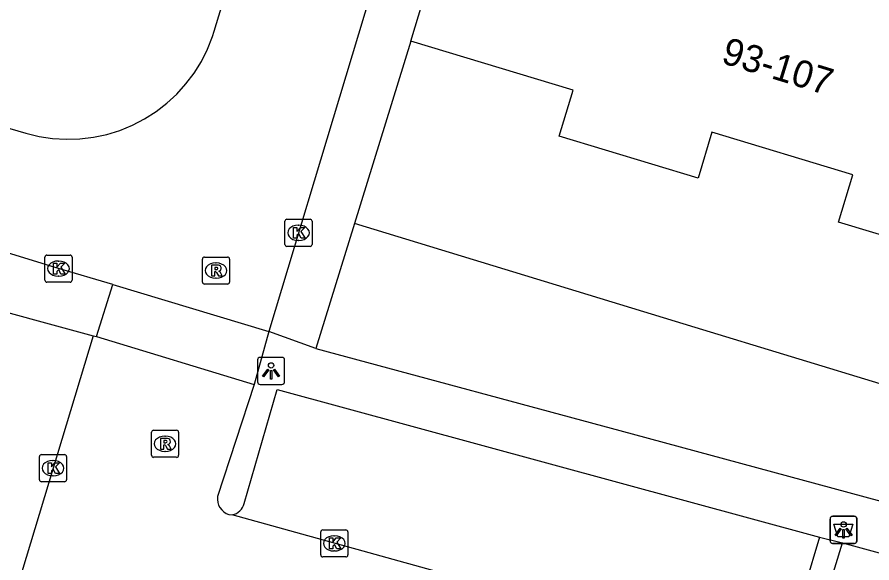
# Model space of a CAD drawing. Extents: x 160304 to 160954, y 383686 to 384161.
# Drawn here: x 160759.25 to 160790.81, y 383754.16 to 383774.29 of the extents above; entities that cross this region are included whole.
import ezdxf

# ---------------------------------------------------------------- set-up
doc = ezdxf.new("R2010")
doc.units = 0
for name, color, linetype in [('IMGEO_Afvalbak', 7, 'Continuous'), ('IMGEO_Groenvoorziening', 7, 'Continuous'), ('IMGEO_Kolk', 7, 'Continuous'), ('IMGEO_Lichtpunt', 7, 'Continuous'), ('IMGEO_Pand', 7, 'Continuous'), ('IMGEO_Pand_nummerreeks', 7, 'Continuous'), ('IMGEO_Rijbaan_lokaal_open', 7, 'Continuous'), ('IMGEO_Rioolput', 7, 'Continuous'), ('IMGEO_Voetpad_open', 7, 'Continuous')]:
    doc.layers.add(name, color=color, linetype=linetype)

msp = doc.modelspace()

# ---------------------------------------------------------------- linework, layer by layer
at = {"layer": 'IMGEO_Afvalbak'}
for p, q in [((160789.267, 383754.975), (160789.267, 383755.775)), ((160789.267, 383755.775), (160789.267, 383754.975)), ((160789.367, 383755.875), (160790.157, 383755.875)), ((160790.157, 383755.875), (160789.367, 383755.875)), ((160790.257, 383755.775), (160790.257, 383754.975)), ((160790.257, 383754.975), (160790.257, 383755.775)), ((160790.157, 383754.875), (160789.367, 383754.875)), ((160789.367, 383754.875), (160790.157, 383754.875))]:
    msp.add_line(p, q, dxfattribs=at)
msp.add_lwpolyline([(160789.41, 383755.589), (160790.114, 383755.589), (160789.965, 383755.119), (160789.559, 383755.119), (160789.41, 383755.589)], dxfattribs=at)
for centre, start, end in [((160789.367, 383755.775), 90, 180), ((160789.367, 383755.775), 90, 180), ((160790.157, 383755.775), 0, 90), ((160790.157, 383755.775), 360, 90), ((160789.367, 383754.975), 180, 270), ((160789.367, 383754.975), 180, 270), ((160790.157, 383754.975), 270, 0), ((160790.157, 383754.975), 270, 0)]:
    msp.add_arc(centre, 0.1, start, end, dxfattribs=at)
at = {"layer": 'IMGEO_Groenvoorziening'}
msp.add_lwpolyline([(160798.517, 383758.511), (160784.286, 383762.843), (160783.114, 383763.2), (160771.703, 383766.673)], dxfattribs=at)
at = {"layer": 'IMGEO_Kolk'}
for p, q in [((160769.214, 383766.835), (160770.066, 383766.835)), ((160769.139, 383765.909), (160769.139, 383766.761)), ((160769.627, 383766.615), (160769.652, 383766.615)), ((160770.14, 383766.761), (160770.14, 383765.909)), ((160769.65, 383766.055), (160769.625, 383766.055)), ((160770.066, 383765.835), (160769.214, 383765.835)), ((160760.275, 383764.587), (160760.275, 383765.439)), ((160760.35, 383765.513), (160761.202, 383765.513)), ((160760.763, 383765.293), (160760.788, 383765.293)), ((160761.276, 383765.439), (160761.276, 383764.587)), ((160760.786, 383764.733), (160760.761, 383764.733)), ((160761.202, 383764.513), (160760.35, 383764.513)), ((160760.072, 383757.226), (160760.072, 383758.078)), ((160760.147, 383758.152), (160760.999, 383758.152)), ((160761.073, 383758.078), (160761.073, 383757.226)), ((160760.56, 383757.932), (160760.585, 383757.932)), ((160760.583, 383757.372), (160760.558, 383757.372)), ((160760.999, 383757.152), (160760.147, 383757.152)), ((160770.46, 383754.45), (160770.46, 383755.302)), ((160770.535, 383755.376), (160771.387, 383755.376)), ((160770.948, 383755.156), (160770.973, 383755.156)), ((160771.461, 383755.302), (160771.461, 383754.45)), ((160770.971, 383754.596), (160770.946, 383754.596)), ((160771.387, 383754.376), (160770.535, 383754.376))]:
    msp.add_line(p, q, dxfattribs=at)
for points in [[(160769.214, 383766.835), (160770.066, 383766.835)], [(160769.139, 383765.909), (160769.139, 383766.761)], [(160769.46, 383766.535), (160769.583, 383766.535), (160769.583, 383766.384), (160769.713, 383766.535), (160769.877, 383766.535), (160769.731, 383766.384), (160769.884, 383766.135), (160769.732, 383766.135), (160769.647, 383766.299), (160769.583, 383766.232), (160769.583, 383766.135), (160769.46, 383766.135), (160769.46, 383766.535)], [(160770.14, 383766.761), (160770.14, 383765.909)], [(160770.066, 383765.835), (160769.214, 383765.835)], [(160760.275, 383764.587), (160760.275, 383765.439)], [(160760.35, 383765.513), (160761.202, 383765.513)], [(160761.276, 383765.439), (160761.276, 383764.587)], [(160760.596, 383765.213), (160760.719, 383765.213), (160760.719, 383765.062), (160760.849, 383765.213), (160761.013, 383765.213), (160760.867, 383765.062), (160761.02, 383764.813), (160760.868, 383764.813), (160760.783, 383764.977), (160760.719, 383764.91), (160760.719, 383764.813), (160760.596, 383764.813), (160760.596, 383765.213)], [(160761.202, 383764.513), (160760.35, 383764.513)], [(160760.072, 383757.226), (160760.072, 383758.078)], [(160760.147, 383758.152), (160760.999, 383758.152)], [(160761.073, 383758.078), (160761.073, 383757.226)], [(160760.393, 383757.852), (160760.516, 383757.852), (160760.516, 383757.701), (160760.646, 383757.852), (160760.81, 383757.852), (160760.664, 383757.701), (160760.817, 383757.452), (160760.665, 383757.452), (160760.58, 383757.616), (160760.516, 383757.549), (160760.516, 383757.452), (160760.393, 383757.452), (160760.393, 383757.852)], [(160760.999, 383757.152), (160760.147, 383757.152)], [(160770.46, 383754.45), (160770.46, 383755.302)], [(160770.535, 383755.376), (160771.387, 383755.376)], [(160771.461, 383755.302), (160771.461, 383754.45)], [(160770.781, 383755.076), (160770.904, 383755.076), (160770.904, 383754.925), (160771.034, 383755.076), (160771.198, 383755.076), (160771.052, 383754.925), (160771.205, 383754.676), (160771.053, 383754.676), (160770.968, 383754.84), (160770.904, 383754.773), (160770.904, 383754.676), (160770.781, 383754.676), (160770.781, 383755.076)], [(160771.387, 383754.376), (160770.535, 383754.376)]]:
    msp.add_lwpolyline(points, dxfattribs=at)
for centre, start, end in [((160769.216, 383766.759), 91.552, 178.448), ((160769.216, 383766.759), 91.552, 178.448), ((160770.064, 383766.759), 1.552, 88.448), ((160770.064, 383766.759), 1.552, 88.448), ((160769.216, 383765.911), 181.552, 268.448), ((160769.216, 383765.911), 181.552, 268.448), ((160770.064, 383765.911), 271.552, 358.448), ((160770.064, 383765.911), 271.552, 358.448), ((160760.352, 383765.437), 91.552, 178.448), ((160760.352, 383765.437), 91.552, 178.448), ((160761.2, 383765.437), 1.552, 88.448), ((160761.2, 383765.437), 1.552, 88.448), ((160760.352, 383764.589), 181.552, 268.448), ((160760.352, 383764.589), 181.552, 268.448), ((160761.2, 383764.589), 271.552, 358.448), ((160761.2, 383764.589), 271.552, 358.448), ((160760.149, 383758.076), 91.552, 178.448), ((160760.149, 383758.076), 91.552, 178.448), ((160760.997, 383758.076), 1.552, 88.448), ((160760.997, 383758.076), 1.552, 88.448), ((160760.149, 383757.228), 181.552, 268.448), ((160760.149, 383757.228), 181.552, 268.448), ((160760.997, 383757.228), 271.552, 358.448), ((160760.997, 383757.228), 271.552, 358.448), ((160770.537, 383755.3), 91.552, 178.448), ((160770.537, 383755.3), 91.552, 178.448), ((160771.385, 383755.3), 1.552, 88.448), ((160771.385, 383755.3), 1.552, 88.448), ((160770.537, 383754.452), 181.552, 268.448), ((160770.537, 383754.452), 181.552, 268.448), ((160771.385, 383754.452), 271.552, 358.448), ((160771.385, 383754.452), 271.552, 358.448)]:
    msp.add_arc(centre, 0.0765, start, end, dxfattribs=at)
for centre, major_axis, ratio, start_param, end_param in [((160769.626, 383766.335), (-0.387, 0.002), 0.722429, 4.712389, 7.853982), ((160769.651, 383766.335), (-0.39, 0.002), 0.717154, 1.570796, 4.712389), ((160760.762, 383765.013), (-0.387, 0.002), 0.722429, 4.712389, 7.853982), ((160760.787, 383765.013), (-0.39, 0.002), 0.717154, 1.570796, 4.712389), ((160760.559, 383757.652), (-0.387, 0.002), 0.722429, 4.712389, 7.853982), ((160760.584, 383757.652), (-0.39, 0.002), 0.717154, 1.570796, 4.712389), ((160770.947, 383754.876), (-0.387, 0.002), 0.722429, 4.712389, 7.853982), ((160770.972, 383754.876), (-0.39, 0.002), 0.717154, 1.570796, 4.712389)]:
    msp.add_ellipse(centre, major_axis=major_axis, ratio=ratio, start_param=start_param, end_param=end_param, dxfattribs=at)
at = {"layer": 'IMGEO_Lichtpunt'}
for p, q in [((160768.127, 383761.645), (160768.127, 383760.838)), ((160768.127, 383761.645), (160768.127, 383760.838)), ((160769.029, 383761.74), (160768.221, 383761.74)), ((160769.029, 383761.74), (160768.221, 383761.74)), ((160769.123, 383760.838), (160769.123, 383761.645)), ((160769.123, 383760.838), (160769.123, 383761.645)), ((160768.221, 383760.744), (160769.029, 383760.744)), ((160768.221, 383760.744), (160769.029, 383760.744)), ((160789.269, 383755.778), (160789.269, 383754.971)), ((160789.269, 383755.778), (160789.269, 383754.971)), ((160790.171, 383755.873), (160789.363, 383755.873)), ((160790.171, 383755.873), (160789.363, 383755.873)), ((160790.265, 383754.971), (160790.265, 383755.778)), ((160790.265, 383754.971), (160790.265, 383755.778)), ((160789.363, 383754.877), (160790.171, 383754.877)), ((160789.363, 383754.877), (160790.171, 383754.877))]:
    msp.add_line(p, q, dxfattribs=at)
for points in [[(160768.501, 383761.309), (160768.54, 383761.281), (160768.352, 383761.019), (160768.314, 383761.046), (160768.501, 383761.309)], [(160768.603, 383761.261), (160768.65, 383761.261), (160768.65, 383760.939), (160768.603, 383760.939), (160768.603, 383761.261)], [(160768.713, 383761.281), (160768.751, 383761.308), (160768.938, 383761.046), (160768.899, 383761.018), (160768.713, 383761.281)], [(160789.643, 383755.442), (160789.682, 383755.414), (160789.494, 383755.152), (160789.456, 383755.179), (160789.643, 383755.442)], [(160789.745, 383755.394), (160789.792, 383755.394), (160789.792, 383755.072), (160789.745, 383755.072), (160789.745, 383755.394)], [(160789.855, 383755.414), (160789.893, 383755.441), (160790.08, 383755.179), (160790.041, 383755.151), (160789.855, 383755.414)]]:
    msp.add_lwpolyline(points, dxfattribs=at)
for centre in [(160768.626, 383761.443), (160789.768, 383755.576)]:
    msp.add_circle(centre, 0.0994, dxfattribs=at)
for centre, start, end in [((160768.221, 383761.645), 90, 180), ((160768.221, 383761.645), 90, 180), ((160769.029, 383761.645), 0, 90), ((160769.029, 383761.645), 0, 90), ((160768.221, 383760.838), 180, 270), ((160768.221, 383760.838), 180, 270), ((160769.029, 383760.838), 270, 0), ((160769.029, 383760.838), 270, 360), ((160789.363, 383755.778), 90, 180), ((160789.363, 383755.778), 90, 180), ((160790.171, 383755.778), 0, 90), ((160790.171, 383755.778), 0, 90), ((160789.363, 383754.971), 180, 270), ((160789.363, 383754.971), 180, 270), ((160790.171, 383754.971), 270, 0), ((160790.171, 383754.971), 270, 360)]:
    msp.add_arc(centre, 0.0946, start, end, dxfattribs=at)
at = {"layer": 'IMGEO_Pand'}
for points in [[(160773.791, 383773.407), (160777.24, 383784.841)], [(160801.23, 383765.073), (160795.16, 383766.904), (160794.646, 383765.201), (160789.577, 383766.73), (160790.104, 383768.477), (160784.903, 383770.046), (160784.393, 383768.357), (160779.268, 383769.903), (160779.78, 383771.6), (160773.791, 383773.407)]]:
    msp.add_lwpolyline(points, dxfattribs=at)
at = {"layer": 'IMGEO_Rijbaan_lokaal_open'}
for points in [[(160757.402, 383770.637), (160759.571, 383770.008), (160760.06, 383769.889), (160760.558, 383769.815), (160761.061, 383769.785), (160761.564, 383769.8), (160762.064, 383769.86), (160762.557, 383769.965), (160763.038, 383770.113), (160763.504, 383770.304), (160763.952, 383770.535), (160764.377, 383770.805), (160764.775, 383771.113), (160765.145, 383771.454), (160765.483, 383771.828), (160765.786, 383772.23), (160766.052, 383772.658), (160766.279, 383773.107), (160766.465, 383773.575), (160766.528, 383773.769), (160772.384, 383792.997)], [(160780.737, 383792.752), (160780.559, 383792.806), (160780.324, 383792.872), (160780.084, 383792.917), (160779.841, 383792.941), (160779.596, 383792.943), (160779.353, 383792.922), (160779.112, 383792.88), (160778.876, 383792.817), (160778.647, 383792.733), (160778.426, 383792.629), (160778.215, 383792.506), (160778.017, 383792.364), (160777.831, 383792.205), (160777.661, 383792.03), (160777.507, 383791.84), (160777.37, 383791.638), (160777.252, 383791.424), (160777.154, 383791.201), (160777.074, 383790.964), (160768.544, 383762.699)], [(160762.78, 383764.428), (160760.777, 383765.014), (160756.154, 383766.428)], [(160762.182, 383762.504), (160762.78, 383764.428)], [(160762.78, 383764.428), (160768.544, 383762.699)], [(160762.054, 383762.539), (160758.251, 383750), (160754.201, 383736.646), (160781.091, 383729.259), (160787.419, 383750), (160787.511, 383750.302), (160767.189, 383755.931)], [(160762.054, 383762.539), (160762.182, 383762.504)], [(160762.182, 383762.504), (160768.001, 383760.742)], [(160768.544, 383762.699), (160768.001, 383760.742)], [(160768.001, 383760.742), (160766.648, 383756.603)], [(160767.067, 383755.943), (160767.189, 383755.931)]]:
    msp.add_lwpolyline(points, dxfattribs=at)
msp.add_arc((160767.258, 383756.527), 0.615, 172.9358, 251.8829, dxfattribs=at)
at = {"layer": 'IMGEO_Rioolput'}
for p, q in [((160766.091, 383764.516), (160766.091, 383765.368)), ((160766.166, 383765.442), (160767.018, 383765.442)), ((160767.092, 383765.368), (160767.092, 383764.516)), ((160766.579, 383765.222), (160766.604, 383765.222)), ((160766.602, 383764.662), (160766.577, 383764.662)), ((160767.018, 383764.442), (160766.166, 383764.442)), ((160764.211, 383758.126), (160764.211, 383758.978)), ((160764.286, 383759.052), (160765.138, 383759.052)), ((160765.212, 383758.978), (160765.212, 383758.126)), ((160764.699, 383758.832), (160764.724, 383758.832)), ((160765.138, 383758.052), (160764.286, 383758.052)), ((160764.722, 383758.272), (160764.697, 383758.272))]:
    msp.add_line(p, q, dxfattribs=at)
for points in [[(160766.091, 383764.516), (160766.091, 383765.368)], [(160766.166, 383765.442), (160767.018, 383765.442)], [(160767.092, 383765.368), (160767.092, 383764.516)], [(160766.68, 383765.14), (160766.428, 383765.142), (160766.428, 383764.742)], [(160766.606, 383765.061), (160766.552, 383765.061), (160766.552, 383764.98)], [(160766.552, 383764.98), (160766.604, 383764.98)], [(160766.428, 383764.742), (160766.552, 383764.742), (160766.552, 383764.904), (160766.563, 383764.904)], [(160766.61, 383764.875), (160766.681, 383764.742), (160766.821, 383764.742), (160766.756, 383764.868)], [(160767.018, 383764.442), (160766.166, 383764.442)], [(160764.211, 383758.126), (160764.211, 383758.978)], [(160764.286, 383759.052), (160765.138, 383759.052)], [(160765.212, 383758.978), (160765.212, 383758.126)], [(160764.8, 383758.75), (160764.548, 383758.752), (160764.548, 383758.352)], [(160764.726, 383758.671), (160764.672, 383758.671), (160764.672, 383758.59)], [(160764.548, 383758.352), (160764.672, 383758.352), (160764.672, 383758.514), (160764.683, 383758.514)], [(160764.672, 383758.59), (160764.724, 383758.59)], [(160764.73, 383758.485), (160764.801, 383758.352), (160764.941, 383758.352), (160764.876, 383758.478)], [(160765.138, 383758.052), (160764.286, 383758.052)]]:
    msp.add_lwpolyline(points, dxfattribs=at)
for centre, radius, start, end in [((160766.168, 383765.366), 0.0765, 91.552, 178.448), ((160766.168, 383765.366), 0.0765, 91.552, 178.448), ((160767.016, 383765.366), 0.0765, 1.552, 88.448), ((160767.016, 383765.366), 0.0765, 1.552, 88.448), ((160766.588, 383765.169), 0.19, 274.7715, 282.9687), ((160766.612, 383764.965), 0.0964, 77.0061, 93.1865), ((160766.626, 383765.022), 0.0378, 276.6634, 79.6772), ((160766.679, 383765.03), 0.109, 350.3612, 89.416), ((160766.677, 383765.03), 0.112, 277.5842, 350.9817), ((160766.562, 383764.851), 0.0533, 26.0293, 88.6989), ((160766.661, 383764.815), 0.108, 29.5134, 73.7905), ((160766.168, 383764.518), 0.0765, 181.552, 268.448), ((160766.168, 383764.518), 0.0765, 181.552, 268.448), ((160767.016, 383764.518), 0.0765, 271.552, 358.448), ((160767.016, 383764.518), 0.0765, 271.552, 358.448), ((160764.288, 383758.976), 0.0765, 91.552, 178.448), ((160764.288, 383758.976), 0.0765, 91.552, 178.448), ((160765.136, 383758.976), 0.0765, 1.552, 88.448), ((160765.136, 383758.976), 0.0765, 1.552, 88.448), ((160764.732, 383758.575), 0.0964, 77.0061, 93.1865), ((160764.746, 383758.632), 0.0378, 276.6634, 79.6772), ((160764.799, 383758.64), 0.109, 350.3612, 89.416), ((160764.797, 383758.64), 0.112, 277.5842, 350.9817), ((160764.682, 383758.461), 0.0533, 26.0293, 88.6989), ((160764.708, 383758.779), 0.19, 274.7715, 282.9687), ((160764.781, 383758.425), 0.108, 29.5134, 73.7905), ((160764.288, 383758.128), 0.0765, 181.552, 268.448), ((160764.288, 383758.128), 0.0765, 181.552, 268.448), ((160765.136, 383758.128), 0.0765, 271.552, 358.448), ((160765.136, 383758.128), 0.0765, 271.552, 358.448)]:
    msp.add_arc(centre, radius, start, end, dxfattribs=at)
for centre, major_axis, ratio, start_param, end_param in [((160766.578, 383764.942), (-0.387, 0.002), 0.722429, 4.712389, 7.853982), ((160766.603, 383764.942), (-0.39, 0.002), 0.717154, 1.570796, 4.712389), ((160764.698, 383758.552), (-0.387, 0.002), 0.722429, 4.712389, 7.853982), ((160764.723, 383758.552), (-0.39, 0.002), 0.717154, 1.570796, 4.712389)]:
    msp.add_ellipse(centre, major_axis=major_axis, ratio=ratio, start_param=start_param, end_param=end_param, dxfattribs=at)
at = {"layer": 'IMGEO_Voetpad_open'}
for points in [[(160773.791, 383773.407), (160771.703, 383766.673)], [(160771.703, 383766.673), (160770.275, 383762.066)], [(160757.219, 383763.851), (160762.054, 383762.539)], [(160770.275, 383762.066), (160768.544, 383762.699)], [(160770.275, 383762.066), (160781.957, 383758.913), (160783.139, 383758.594), (160797.372, 383754.752)], [(160767.636, 383756.353), (160768.846, 383760.554), (160788.876, 383755.105)], [(160788.876, 383755.105), (160787.818, 383751.564)], [(160788.696, 383751.53), (160789.723, 383754.903)], [(160788.876, 383755.105), (160789.723, 383754.903)], [(160789.723, 383754.903), (160801.112, 383751.801)]]:
    msp.add_lwpolyline(points, dxfattribs=at)
msp.add_arc((160767.093, 383756.481), 0.558, 279.9191, 346.7851, dxfattribs=at)

# ---------------------------------------------------------------- texts
at = {"layer": 'IMGEO_Pand_nummerreeks'}
msp.add_text('93-107', height=1, rotation=342.922, dxfattribs=at).set_placement((160785.209, 383772.613))

doc.saveas('drawing.dxf')
